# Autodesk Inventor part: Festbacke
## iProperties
Created: 2008-02
Part Number: Festbacke
Document SubType Name: Modeling
Designer: Benno
Manufacturer: Standard
Standards Organization: Custom
Author: Benno
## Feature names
1. Extrusion1
2. Bohrung1 [Hole]
